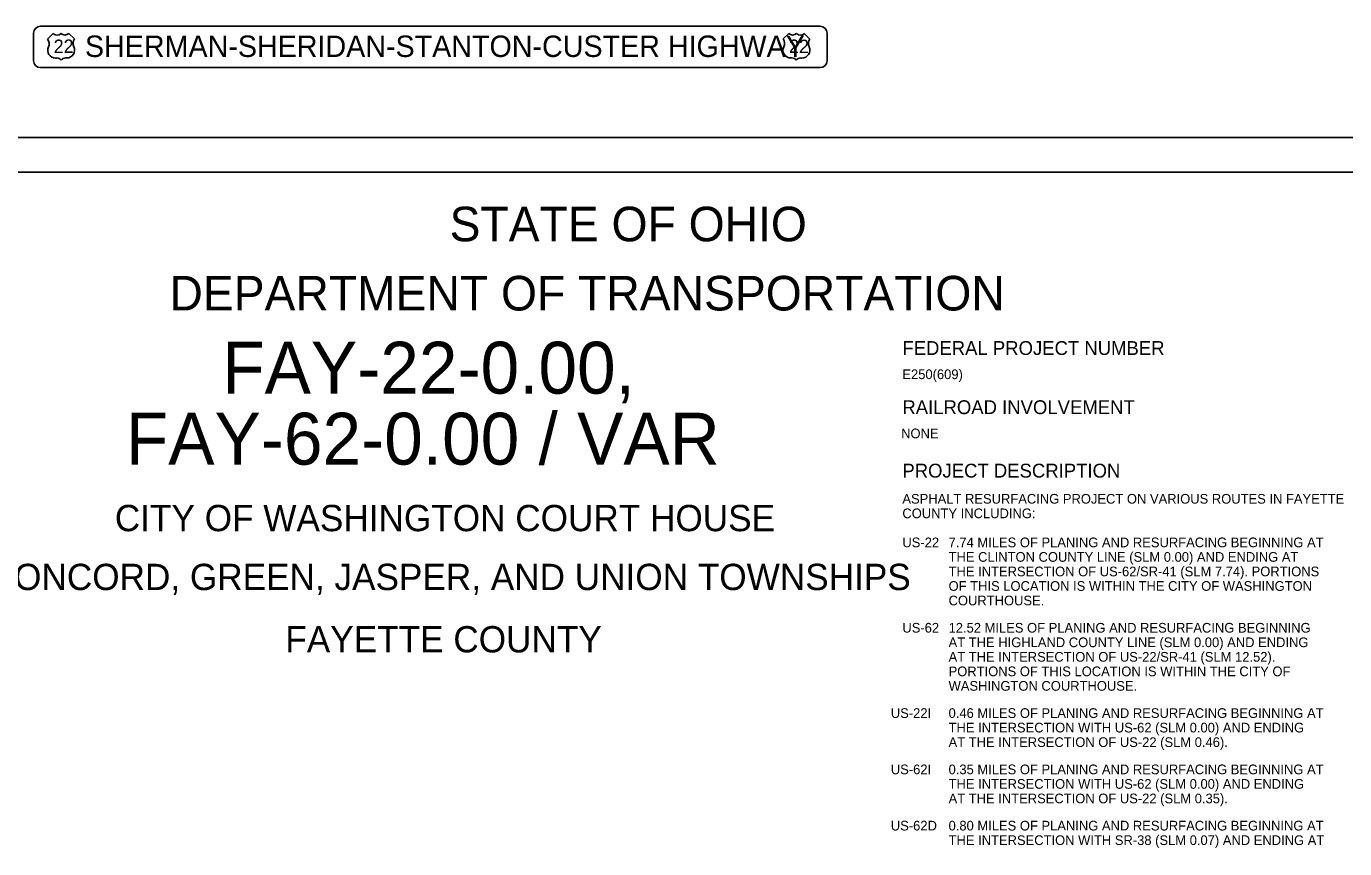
# Model space of a CAD drawing. Extents: x -12 to 164, y -741 to 24.
# Drawn here: x 12.93 to 31.99, y 11.72 to 23.61 of the extents above; entities that cross this region are included whole.
import ezdxf

# ---------------------------------------------------------------- set-up
doc = ezdxf.new("R2010")
doc.units = 0
for name, color, linetype in [('Default', 7, 'Continuous'), ('PM_P_Stop_Line', 7, 'Continuous'), ('PM_X_CL_Pass_Proh_Rt', 7, 'Continuous'), ('SC_Scratch1', 7, 'Continuous'), ('SH_Border', 7, 'Continuous'), ('SH_Cut_Line', 7, 'Continuous')]:
    doc.layers.add(name, color=color, linetype=linetype)

msp = doc.modelspace()

# ---------------------------------------------------------------- linework, layer by layer
at = {"layer": 'PM_P_Stop_Line'}
for p, q in [((13.322, 23.503), (13.242, 23.422)), ((13.628, 23.425), (13.547, 23.505)), ((23.872, 23.425), (23.953, 23.505)), ((24.178, 23.503), (24.258, 23.422)), ((13.357, 23.149), (13.373, 23.149)), ((13.502, 23.15), (13.518, 23.151)), ((23.998, 23.15), (23.982, 23.151)), ((24.143, 23.149), (24.127, 23.149))]:
    msp.add_line(p, q, dxfattribs=at)
for centre, radius, start, end in [((13.378, 23.561), 0.0805, 226.1115, 314.9656), ((13.49, 23.562), 0.0805, 226.1115, 314.9656), ((24.01, 23.562), 0.0805, 225.0344, 313.8885), ((24.123, 23.561), 0.0805, 225.0344, 313.8885), ((13.15, 23.356), 0.113, 335.0857, 35.5395), ((13.355, 23.262), 0.113, 155.3705, 271.1768), ((13.518, 23.263), 0.113, 269.9003, 25.7066), ((13.721, 23.361), 0.113, 145.5376, 205.9914), ((23.982, 23.263), 0.113, 154.2934, 270.0997), ((23.779, 23.361), 0.113, 334.0086, 34.4624), ((24.145, 23.262), 0.113, 268.8232, 24.6295), ((24.35, 23.356), 0.113, 144.4605, 204.9143), ((13.374, 23.069), 0.0805, 37.4084, 90.5385), ((13.503, 23.07), 0.0805, 90.5385, 143.6686), ((23.997, 23.07), 0.0805, 36.3314, 89.4615), ((24.126, 23.069), 0.0805, 89.4615, 142.5916)]:
    msp.add_arc(centre, radius, start, end, dxfattribs=at)
at = {"layer": 'SC_Scratch1'}
for p, q in [((13.037, 23.11), (13.037, 23.507)), ((13.137, 23.607), (24.407, 23.607)), ((24.507, 23.507), (24.507, 23.11)), ((24.407, 23.01), (13.137, 23.01))]:
    msp.add_line(p, q, dxfattribs=at)
for centre, start, end in [((13.137, 23.507), 90, 180), ((24.407, 23.507), 0, 90), ((13.137, 23.11), 180, 270), ((24.407, 23.11), 270, 0)]:
    msp.add_arc(centre, 0.1, start, end, dxfattribs=at)
at = {"layer": 'SH_Border'}
msp.add_lwpolyline([(1.5, 21.5), (33.5, 21.5), (33.5, 0.5), (1.5, 0.5)], close=True, dxfattribs=at)
at = {"layer": 'SH_Cut_Line'}
msp.add_lwpolyline([(0, 0), (34, 0), (34, 22), (0, 22)], close=True, dxfattribs=at)

# ---------------------------------------------------------------- texts
at = {"layer": 'Default'}
for s, p in [('ASPHALT RESURFACING PROJECT ON VARIOUS ROUTES IN FAYETTE ', (25.595, 16.708)), ('COUNTY INCLUDING:', (25.595, 16.498)), ('US-22', (25.595, 16.078)), ('US-62', (25.595, 14.844)), ('US-22', (25.428, 13.611)), ('I', (25.96, 13.611)), ('US-62', (25.428, 12.797)), ('I', (25.96, 12.797)), ('US-62', (25.428, 11.984)), ('D', (25.96, 11.984))]:
    msp.add_text(s, height=0.14, dxfattribs=at).set_placement(p)
at = {"layer": 'PM_P_Stop_Line'}
for rotation, p in [(0.5385, (13.33, 23.221)), (359.4615, (23.956, 23.223))]:
    msp.add_text('22', height=0.1932, rotation=rotation, dxfattribs=at).set_placement(p)
at = {"layer": 'PM_X_CL_Pass_Proh_Rt'}
for s, p in [('7.74 MILES OF PLANING AND RESURFACING BEGINNING AT ', (26.263, 16.078)), ('THE CLINTON COUNTY LINE (SLM 0.00) AND ENDING AT ', (26.263, 15.868)), ('THE INTERSECTION OF US-62/SR-41 (SLM 7.74). PORTIONS ', (26.263, 15.658)), ('OF THIS LOCATION IS WITHIN THE CITY OF WASHINGTON ', (26.263, 15.448)), ('COURTHOUSE.', (26.263, 15.238)), ('12.52 MILES OF PLANING AND RESURFACING BEGINNING ', (26.263, 14.844)), ('AT THE HIGHLAND COUNTY LINE (SLM 0.00) AND ENDING ', (26.263, 14.634)), ('AT THE INTERSECTION OF US-22/SR-41 (SLM 12.52). ', (26.263, 14.424)), ('PORTIONS OF THIS LOCATION IS WITHIN THE CITY OF ', (26.263, 14.214)), ('WASHINGTON COURTHOUSE.', (26.263, 14.004)), ('0.46 MILES OF PLANING AND RESURFACING BEGINNING AT ', (26.263, 13.611)), ('THE INTERSECTION WITH US-62 (SLM 0.00) AND ENDING ', (26.263, 13.401)), ('AT THE INTERSECTION OF US-22 (SLM 0.46). ', (26.263, 13.191)), ('0.35 MILES OF PLANING AND RESURFACING BEGINNING AT ', (26.263, 12.797)), ('THE INTERSECTION WITH US-62 (SLM 0.00) AND ENDING ', (26.263, 12.587)), ('AT THE INTERSECTION OF US-22 (SLM 0.35). ', (26.263, 12.377)), ('0.80 MILES OF PLANING AND RESURFACING BEGINNING AT ', (26.263, 11.984)), ('THE INTERSECTION WITH SR-38 (SLM 0.07) AND ENDING AT ', (26.263, 11.774))]:
    msp.add_text(s, height=0.14, dxfattribs=at).set_placement(p)
at = {"layer": 'SC_Scratch1'}
for s, height, p in [('SHERMAN-SHERIDAN-STANTON-CUSTER HIGHWAY', 0.30984, (13.781, 23.164)), ('STATE OF OHIO', 0.5, (19.051, 20.5)), ('DEPARTMENT OF TRANSPORTATION', 0.5, (15.002, 19.5)), ('FAY-22-0.00,', 0.75, (15.765, 18.298)), ('FEDERAL PROJECT NUMBER', 0.2, (25.595, 18.857)), ('E250(609)', 0.14, (25.595, 18.508)), ('RAILROAD INVOLVEMENT', 0.2, (25.595, 18.002)), ('FAY-62-0.00 / VAR', 0.75, (14.372, 17.272)), ('NONE', 0.14, (25.577, 17.653)), ('PROJECT DESCRIPTION', 0.2, (25.595, 17.085)), ('CITY OF WASHINGTON COURT HOUSE', 0.38, (14.213, 16.31)), ('CONCORD, GREEN, JASPER, AND UNION TOWNSHIPS', 0.38, (12.39, 15.459)), ('FAYETTE COUNTY', 0.38, (16.677, 14.558))]:
    msp.add_text(s, height=height, dxfattribs=at).set_placement(p)

doc.saveas('drawing.dxf')
